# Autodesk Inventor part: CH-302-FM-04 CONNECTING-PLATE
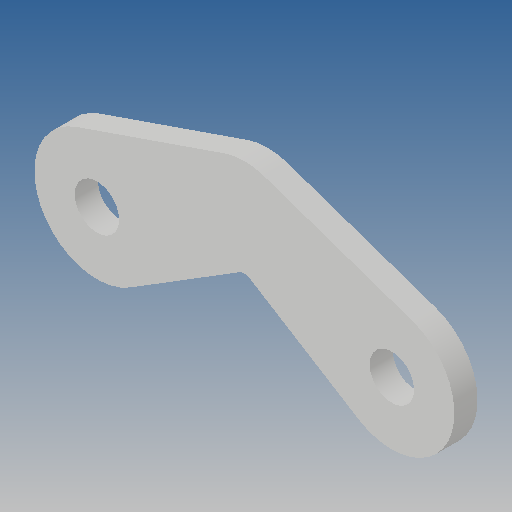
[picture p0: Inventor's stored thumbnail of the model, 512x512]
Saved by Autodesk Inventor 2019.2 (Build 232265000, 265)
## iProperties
Created: 2013-03
Part Number: CH-302-FM-04 CONNECTING-PLATE
Material: Ogólny
Document SubType Name: Modeling
Designer: CADENGINEERING4
Density: 1 g/cm^3
Appearance: Domyślna
Author: CADENGINEERING4
Revision Number: ÈÎºÎ
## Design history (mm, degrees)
feature "Í¹Ì¨-À­Éì3"
node "Bryła1"
